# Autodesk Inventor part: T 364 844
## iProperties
Company: Mayer & Müller AG Schaltgeräte
Created: 2005-10
Part Number: T 364 844
Material: 1.0120
Document SubType Name: Modeling
Designer: I.Baliuc
Manufacturer: Standard
Standards Organization: Custom
Description: Seitenblech
Density: 7.85 g/cm^3
Zweck: Rohrtraverse Trener
Author: T.Messerschmitt
Revision Number: 364844
Keywords: 383177
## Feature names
1. Extrusion2
2. Bohrung1 [Hole]
3. Bohrung2 [Hole]
